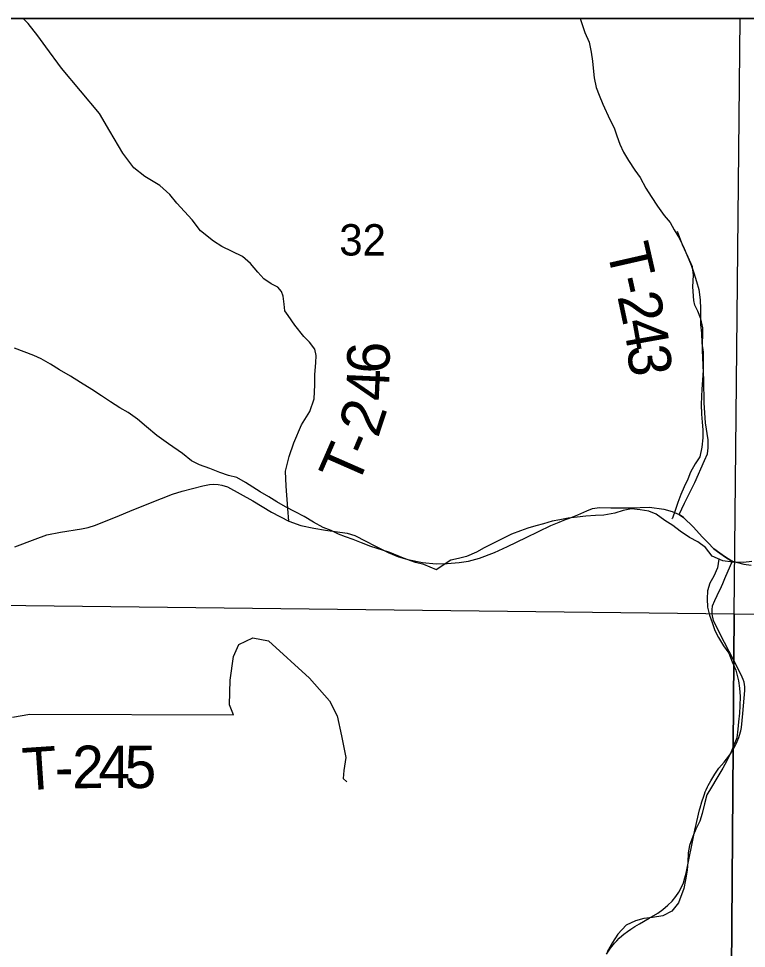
# Model space of a CAD drawing. Extents: x 0 to 34, y 0 to 22.
# Drawn here: x 6.51 to 7.482, y 19.658 to 20.9 of the extents above; entities that cross this region are included whole.
import ezdxf

# ---------------------------------------------------------------- set-up
doc = ezdxf.new("R2010")
doc.units = 0
for name, color, linetype in [('Default', 7, 'Continuous'), ('GM_X_County_Road', 7, 'Continuous'), ('GM_X_Minor_River', 7, 'Continuous'), ('GM_X_Section', 7, 'Continuous'), ('GM_X_Section_Text', 7, 'Continuous'), ('GM_X_Township_Road', 7, 'Continuous'), ('GM_X_Township_Road_Text', 7, 'Continuous'), ('SH_Cut_Line', 7, 'Continuous'), ('SH_Data', 7, 'Continuous')]:
    doc.layers.add(name, color=color, linetype=linetype)

msp = doc.modelspace()

# ---------------------------------------------------------------- linework, layer by layer
at = {"layer": 'Default'}
for p, q in [((7.8225, 20.9), (2.1, 20.9)), ((7.4735, 20.9), (6.4715, 20.9)), ((7.4653, 20.105), (7.4735, 20.9)), ((6.4665, 20.1167), (7.4653, 20.105))]:
    msp.add_line(p, q, dxfattribs=at)
at = {"layer": 'GM_X_County_Road'}
for p, q in [((6.7559, 20.2762), (6.7645, 20.2777)), ((6.7645, 20.2777), (6.77, 20.2781)), ((6.77, 20.2781), (6.7761, 20.2778)), ((6.7761, 20.2778), (6.7811, 20.277)), ((6.7811, 20.277), (6.7889, 20.2745)), ((6.6857, 20.2532), (6.7154, 20.2651)), ((6.7154, 20.2651), (6.7281, 20.2688)), ((6.7281, 20.2688), (6.7559, 20.2762)), ((6.7889, 20.2745), (6.8225, 20.2562)), ((6.6582, 20.2421), (6.6857, 20.2532)), ((6.8225, 20.2562), (6.8476, 20.2408)), ((6.6446, 20.2362), (6.6582, 20.2421)), ((6.8476, 20.2408), (6.8706, 20.2289)), ((7.2568, 20.2375), (7.2686, 20.2426)), ((7.2686, 20.2426), (7.2763, 20.2456)), ((7.2763, 20.2456), (7.2854, 20.247)), ((7.2854, 20.247), (7.3005, 20.2468)), ((7.3005, 20.2468), (7.3268, 20.2468)), ((7.3268, 20.2468), (7.3523, 20.2474)), ((7.3523, 20.2474), (7.3714, 20.2447)), ((7.3714, 20.2447), (7.3824, 20.2417)), ((7.3824, 20.2417), (7.3921, 20.2376)), ((6.6124, 20.2233), (6.6446, 20.2362)), ((6.8706, 20.2289), (6.8868, 20.2232)), ((7.2207, 20.2231), (7.2318, 20.2277)), ((7.2318, 20.2277), (7.2401, 20.2309)), ((7.2401, 20.2309), (7.2456, 20.233)), ((7.2456, 20.233), (7.2568, 20.2375)), ((7.3921, 20.2376), (7.3976, 20.2336)), ((7.3976, 20.2336), (7.411, 20.221)), ((6.5658, 20.214), (6.5935, 20.2187)), ((6.5935, 20.2187), (6.6028, 20.2202)), ((6.6028, 20.2202), (6.6124, 20.2233)), ((6.8868, 20.2232), (6.9038, 20.2194)), ((6.9038, 20.2194), (6.9197, 20.217)), ((6.9197, 20.217), (6.9484, 20.2127)), ((7.1877, 20.2069), (7.2207, 20.2231)), ((7.411, 20.221), (7.4227, 20.2079)), ((6.5048, 20.1945), (6.5319, 20.205)), ((6.5319, 20.205), (6.5475, 20.2104)), ((6.5475, 20.2104), (6.5658, 20.214)), ((6.9484, 20.2127), (6.9587, 20.2096)), ((6.9587, 20.2096), (6.9735, 20.2021)), ((7.1628, 20.1948), (7.1877, 20.2069)), ((7.4227, 20.2079), (7.4302, 20.2002)), ((6.9735, 20.2021), (6.9853, 20.1961)), ((6.9853, 20.1961), (7.0035, 20.1868)), ((7.1453, 20.1868), (7.1628, 20.1948)), ((7.4302, 20.2002), (7.4382, 20.1919)), ((7.4382, 20.1919), (7.4462, 20.1862)), ((7.0035, 20.1868), (7.0173, 20.1814)), ((7.0173, 20.1814), (7.0295, 20.1775)), ((7.1107, 20.1755), (7.1254, 20.1793)), ((7.1254, 20.1793), (7.1453, 20.1868)), ((7.4462, 20.1862), (7.4539, 20.1807)), ((7.4539, 20.1807), (7.461, 20.1765)), ((7.0295, 20.1775), (7.0492, 20.1736)), ((7.0492, 20.1736), (7.0675, 20.172)), ((7.0675, 20.172), (7.082, 20.1723)), ((7.082, 20.1723), (7.0979, 20.1735)), ((7.0979, 20.1735), (7.1107, 20.1755)), ((7.461, 20.1765), (7.463, 20.1753)), ((7.463, 20.1753), (7.4784, 20.1716)), ((7.4784, 20.1716), (7.4881, 20.1701))]:
    msp.add_line(p, q, dxfattribs=at)
at = {"layer": 'GM_X_Minor_River'}
for p, q in [((7.2598, 20.9), (7.261, 20.8959)), ((7.261, 20.8959), (7.2659, 20.8815)), ((7.2659, 20.8815), (7.2716, 20.8684)), ((7.2716, 20.8684), (7.2743, 20.8552)), ((7.2743, 20.8552), (7.2761, 20.843)), ((7.2761, 20.843), (7.2771, 20.8336)), ((7.2771, 20.8336), (7.2786, 20.8207)), ((7.2786, 20.8207), (7.2813, 20.8078)), ((7.2813, 20.8078), (7.2849, 20.7976)), ((7.2849, 20.7976), (7.2898, 20.7856)), ((7.2898, 20.7856), (7.2995, 20.7653)), ((7.2995, 20.7653), (7.3051, 20.7541)), ((7.3051, 20.7541), (7.3088, 20.7435)), ((7.3088, 20.7435), (7.3126, 20.7322)), ((7.3126, 20.7322), (7.3174, 20.7217)), ((7.3174, 20.7217), (7.3242, 20.7105)), ((7.3242, 20.7105), (7.3329, 20.6978)), ((7.3329, 20.6978), (7.34, 20.6877)), ((7.34, 20.6877), (7.3476, 20.6734)), ((7.3476, 20.6734), (7.3544, 20.6622)), ((7.3544, 20.6622), (7.3631, 20.6495)), ((7.3631, 20.6495), (7.3718, 20.6372)), ((7.3718, 20.6372), (7.38, 20.6275)), ((7.38, 20.6275), (7.3852, 20.6178)), ((7.3852, 20.6178), (7.3924, 20.6062)), ((7.3924, 20.6062), (7.3988, 20.5931)), ((7.3988, 20.5931), (7.4037, 20.5814)), ((7.4037, 20.5814), (7.4078, 20.5709)), ((7.4078, 20.5709), (7.4115, 20.5603)), ((7.4115, 20.5603), (7.4149, 20.549)), ((7.4149, 20.549), (7.4182, 20.5381)), ((7.4182, 20.5381), (7.4201, 20.5244)), ((7.4201, 20.5244), (7.4204, 20.5126)), ((7.4204, 20.5126), (7.4203, 20.5031)), ((7.4203, 20.5031), (7.4206, 20.4917)), ((7.4206, 20.4917), (7.4217, 20.48)), ((7.4217, 20.48), (7.4224, 20.4667)), ((7.4224, 20.4667), (7.4239, 20.4545)), ((6.5171, 20.4551), (6.504, 20.46)), ((6.5298, 20.4502), (6.5171, 20.4551)), ((7.4239, 20.4545), (7.4238, 20.4439)), ((6.5398, 20.4455), (6.5298, 20.4502)), ((6.5522, 20.4383), (6.5398, 20.4455)), ((7.4238, 20.4439), (7.4238, 20.4306)), ((6.5642, 20.4311), (6.5522, 20.4383)), ((6.579, 20.4224), (6.5642, 20.4311)), ((7.4238, 20.4306), (7.423, 20.4172)), ((6.5925, 20.4141), (6.579, 20.4224)), ((6.6076, 20.4047), (6.5925, 20.4141)), ((7.423, 20.4172), (7.4222, 20.4051)), ((6.6205, 20.3964), (6.6076, 20.4047)), ((7.4222, 20.4051), (7.4217, 20.3952)), ((6.6325, 20.3884), (6.6205, 20.3964)), ((7.4217, 20.3952), (7.4213, 20.3845)), ((6.6449, 20.3804), (6.6325, 20.3884)), ((6.6558, 20.3739), (6.6449, 20.3804)), ((7.4213, 20.3845), (7.422, 20.3716)), ((6.6686, 20.3652), (6.6558, 20.3739)), ((6.6803, 20.3549), (6.6686, 20.3652)), ((7.422, 20.3716), (7.4227, 20.361)), ((6.6944, 20.3432), (6.6803, 20.3549)), ((7.4227, 20.361), (7.4237, 20.3507)), ((6.7099, 20.3323), (6.6944, 20.3432)), ((7.4236, 20.3401), (7.4224, 20.3275)), ((7.4237, 20.3507), (7.4236, 20.3401)), ((6.7286, 20.3192), (6.7099, 20.3323)), ((7.4224, 20.3275), (7.4197, 20.3149)), ((6.7407, 20.3093), (6.7286, 20.3192)), ((7.4197, 20.3149), (7.4135, 20.3052)), ((6.7515, 20.3039), (6.7407, 20.3093)), ((6.7649, 20.299), (6.7515, 20.3039)), ((7.4135, 20.3052), (7.407, 20.2944)), ((6.7784, 20.2937), (6.7649, 20.299)), ((6.7899, 20.2899), (6.7784, 20.2937)), ((6.8011, 20.2872), (6.7899, 20.2899)), ((7.407, 20.2944), (7.4035, 20.2848)), ((6.8127, 20.2807), (6.8011, 20.2872)), ((6.8224, 20.2742), (6.8127, 20.2807)), ((7.4035, 20.2848), (7.3988, 20.2747)), ((6.8325, 20.268), (6.8224, 20.2742)), ((6.8437, 20.2612), (6.8325, 20.268)), ((7.3988, 20.2747), (7.3941, 20.2643)), ((6.8545, 20.2547), (6.8437, 20.2612)), ((6.8662, 20.2478), (6.8545, 20.2547)), ((7.3902, 20.254), (7.3867, 20.2432)), ((7.3941, 20.2643), (7.3902, 20.254)), ((6.8789, 20.2414), (6.8662, 20.2478)), ((6.8913, 20.2349), (6.8789, 20.2414)), ((7.3172, 20.2432), (7.3059, 20.2395)), ((7.3285, 20.2451), (7.3172, 20.2432)), ((7.34, 20.2442), (7.3285, 20.2451)), ((7.3514, 20.2423), (7.34, 20.2442)), ((7.3614, 20.238), (7.3514, 20.2423)), ((7.3867, 20.2432), (7.3832, 20.2329)), ((6.9037, 20.2277), (6.8913, 20.2349)), ((6.9164, 20.2205), (6.9037, 20.2277)), ((7.2222, 20.2289), (7.2109, 20.2255)), ((7.2324, 20.2307), (7.2222, 20.2289)), ((7.2437, 20.2329), (7.2324, 20.2307)), ((7.2555, 20.2343), (7.2437, 20.2329)), ((7.2672, 20.2354), (7.2555, 20.2343)), ((7.2801, 20.2362), (7.2672, 20.2354)), ((7.2915, 20.2368), (7.2801, 20.2362)), ((7.3059, 20.2395), (7.2915, 20.2368)), ((7.3727, 20.2299), (7.3614, 20.238)), ((7.3835, 20.223), (7.3727, 20.2299)), ((7.3832, 20.2329), (7.3821, 20.2321)), ((6.9272, 20.2163), (6.9164, 20.2205)), ((6.9369, 20.2116), (6.9272, 20.2163)), ((7.18, 20.2159), (7.1679, 20.2114)), ((7.1898, 20.2193), (7.18, 20.2159)), ((7.2007, 20.2226), (7.1898, 20.2193)), ((7.2109, 20.2255), (7.2007, 20.2226)), ((7.3932, 20.2153), (7.3835, 20.223)), ((7.4056, 20.2072), (7.3932, 20.2153)), ((6.9465, 20.2081), (6.9369, 20.2116)), ((6.9565, 20.2042), (6.9465, 20.2081)), ((6.9677, 20.1997), (6.9565, 20.2042)), ((7.1679, 20.2114), (7.1439, 20.1994)), ((7.4171, 20.2011), (7.4056, 20.2072)), ((6.98, 20.1951), (6.9677, 20.1997)), ((6.9957, 20.1899), (6.98, 20.1951)), ((7.1316, 20.1933), (7.1211, 20.1874)), ((7.1439, 20.1994), (7.1316, 20.1933)), ((7.4272, 20.1937), (7.4171, 20.2011)), ((7.4359, 20.1822), (7.4272, 20.1937)), ((7.0053, 20.1868), (6.9957, 20.1899)), ((7.0238, 20.1794), (7.0053, 20.1868)), ((7.0396, 20.1738), (7.0238, 20.1794)), ((7.0974, 20.1791), (7.0868, 20.1769)), ((7.1079, 20.1817), (7.0974, 20.1791)), ((7.1211, 20.1874), (7.1079, 20.1817)), ((7.4501, 20.1757), (7.4359, 20.1822)), ((7.445, 20.1781), (7.4432, 20.1664)), ((7.0507, 20.1711), (7.0396, 20.1738)), ((7.0677, 20.1637), (7.0507, 20.1711)), ((7.0868, 20.1769), (7.0676, 20.1637)), ((7.4432, 20.1664), (7.4382, 20.1556)), ((7.4631, 20.1742), (7.4501, 20.1757)), ((7.4779, 20.1738), (7.4631, 20.1742)), ((7.4889, 20.1749), (7.4779, 20.1738)), ((7.4382, 20.1556), (7.4327, 20.146)), ((7.4327, 20.146), (7.43, 20.1356)), ((7.43, 20.1356), (7.4295, 20.125)), ((7.4295, 20.125), (7.4298, 20.1139)), ((7.4298, 20.1139), (7.4324, 20.1034)), ((7.4324, 20.1034), (7.436, 20.0936)), ((7.436, 20.0936), (7.4398, 20.083)), ((7.4398, 20.083), (7.4446, 20.0733)), ((7.4446, 20.0733), (7.451, 20.0624)), ((7.451, 20.0624), (7.4581, 20.0527)), ((7.4581, 20.0527), (7.4629, 20.0411)), ((7.4629, 20.0411), (7.4678, 20.0298)), ((7.4678, 20.0298), (7.4712, 20.0158)), ((7.4712, 20.0158), (7.4726, 20.0059)), ((7.4726, 20.0059), (7.4733, 19.9946)), ((7.4733, 19.9946), (7.4729, 19.9824)), ((7.4729, 19.9824), (7.4724, 19.9725)), ((7.4724, 19.9725), (7.4712, 19.9607)), ((7.4712, 19.9607), (7.4703, 19.9511)), ((7.4703, 19.9511), (7.4688, 19.9393)), ((7.4652, 19.9297), (7.4606, 19.9185)), ((7.4688, 19.9393), (7.4652, 19.9297)), ((7.4606, 19.9185), (7.4555, 19.9089)), ((7.4555, 19.9089), (7.4501, 19.8992)), ((7.4501, 19.8992), (7.4421, 19.8857)), ((7.4421, 19.8857), (7.4352, 19.8737)), ((7.4352, 19.8737), (7.429, 19.8633)), ((7.429, 19.8633), (7.4256, 19.8514)), ((7.4256, 19.8514), (7.4229, 19.8384)), ((7.4229, 19.8384), (7.4194, 19.828)), ((7.4143, 19.8176), (7.41, 19.8076)), ((7.4194, 19.828), (7.4143, 19.8176)), ((7.41, 19.8076), (7.4058, 19.7957)), ((7.4058, 19.7957), (7.4038, 19.7858)), ((7.4038, 19.7858), (7.4034, 19.7736)), ((7.4034, 19.7736), (7.4025, 19.7629)), ((7.4025, 19.7629), (7.4002, 19.7499)), ((7.4002, 19.7499), (7.3982, 19.7381)), ((7.3982, 19.7381), (7.3912, 19.7193)), ((7.3912, 19.7193), (7.3823, 19.708)), ((7.3823, 19.708), (7.37, 19.702)), ((7.3337, 19.6953), (7.3213, 19.6892)), ((7.3446, 19.6982), (7.3337, 19.6953)), ((7.3564, 19.6997), (7.3446, 19.6982)), ((7.37, 19.702), (7.3564, 19.6997)), ((7.3213, 19.6892), (7.3102, 19.6775)), ((7.3102, 19.6775), (7.3029, 19.6663)), ((7.3029, 19.6663), (7.2957, 19.6535))]:
    msp.add_line(p, q, dxfattribs=at)
at = {"layer": 'GM_X_Section'}
for p, q in [((6.4665, 20.1167), (7.4653, 20.105)), ((7.4653, 20.105), (7.4585, 19.1081)), ((7.4585, 19.1081), (7.4653, 20.105)), ((7.4653, 20.105), (8.4603, 20.0986))]:
    msp.add_line(p, q, dxfattribs=at)
at = {"layer": 'GM_X_Township_Road'}
for p, q in [((6.5226, 20.8933), (6.5158, 20.9)), ((6.5353, 20.8771), (6.5226, 20.8933)), ((6.5462, 20.8621), (6.5353, 20.8771)), ((6.567, 20.8337), (6.5462, 20.8621)), ((6.6178, 20.7731), (6.567, 20.8337)), ((6.6317, 20.7498), (6.6178, 20.7731)), ((6.6487, 20.7204), (6.6317, 20.7498)), ((6.6636, 20.7009), (6.6487, 20.7204)), ((6.6782, 20.6892), (6.6636, 20.7009)), ((6.6982, 20.6772), (6.6782, 20.6892)), ((6.7115, 20.6653), (6.6982, 20.6772)), ((6.7211, 20.6534), (6.7115, 20.6653)), ((6.7416, 20.6313), (6.7211, 20.6534)), ((6.7526, 20.6166), (6.7416, 20.6313)), ((6.7698, 20.6026), (6.7526, 20.6166)), ((7.3964, 20.5977), (7.3897, 20.6159)), ((6.7811, 20.5956), (6.7698, 20.6026)), ((6.8088, 20.5825), (6.7811, 20.5956)), ((7.4041, 20.5814), (7.3964, 20.5977)), ((6.8196, 20.5729), (6.8088, 20.5825)), ((7.4099, 20.5683), (7.4041, 20.5814)), ((6.8292, 20.5615), (6.8196, 20.5729)), ((7.411, 20.5574), (7.4099, 20.5683)), ((6.8372, 20.5525), (6.8292, 20.5615)), ((6.8472, 20.5459), (6.8372, 20.5525)), ((7.4104, 20.542), (7.411, 20.5574)), ((6.8557, 20.5412), (6.8472, 20.5459)), ((6.8608, 20.5354), (6.8557, 20.5412)), ((7.4116, 20.5237), (7.4104, 20.542)), ((6.8629, 20.5295), (6.8608, 20.5354)), ((6.8644, 20.5188), (6.8629, 20.5295)), ((6.8651, 20.5097), (6.8644, 20.5188)), ((7.413, 20.5171), (7.4116, 20.5237)), ((7.4167, 20.5091), (7.413, 20.5171)), ((6.8698, 20.5035), (6.8651, 20.5097)), ((6.8787, 20.4905), (6.8698, 20.5035)), ((7.4207, 20.4991), (7.4167, 20.5091)), ((6.8905, 20.4756), (6.8787, 20.4905)), ((7.4236, 20.4871), (7.4207, 20.4991)), ((6.8983, 20.4679), (6.8905, 20.4756)), ((7.4233, 20.4573), (7.4236, 20.4871)), ((6.9053, 20.4586), (6.8983, 20.4679)), ((6.9073, 20.4501), (6.9053, 20.4586)), ((7.4247, 20.4173), (7.4233, 20.4573)), ((6.9052, 20.4246), (6.9066, 20.4401)), ((6.9066, 20.4401), (6.9073, 20.4501)), ((6.9055, 20.4111), (6.9052, 20.4246)), ((7.4253, 20.3867), (7.4247, 20.4173)), ((6.9044, 20.3923), (6.9055, 20.4111)), ((6.8986, 20.3753), (6.9044, 20.3923)), ((7.4273, 20.3603), (7.4253, 20.3867)), ((6.8876, 20.3573), (6.8986, 20.3753)), ((6.8774, 20.3334), (6.8876, 20.3573)), ((7.4308, 20.3375), (7.4273, 20.3603)), ((6.8711, 20.3151), (6.8774, 20.3334)), ((7.4296, 20.3186), (7.4308, 20.3269)), ((7.4308, 20.3269), (7.4308, 20.3375)), ((6.8662, 20.2956), (6.8711, 20.3151)), ((7.4259, 20.3097), (7.4296, 20.3186)), ((7.4127, 20.2805), (7.4259, 20.3097)), ((6.8671, 20.2758), (6.8662, 20.2956)), ((7.3993, 20.2531), (7.4127, 20.2805)), ((6.8691, 20.2459), (6.8671, 20.2758)), ((7.3921, 20.2376), (7.3993, 20.2531)), ((6.8706, 20.2289), (6.8691, 20.2459)), ((7.3976, 20.2336), (7.3921, 20.2376)), ((7.411, 20.221), (7.3976, 20.2336)), ((7.4227, 20.2079), (7.411, 20.221)), ((7.4302, 20.2002), (7.4227, 20.2079)), ((7.4382, 20.1919), (7.4302, 20.2002)), ((7.4462, 20.1862), (7.4382, 20.1919)), ((7.4539, 20.1807), (7.4462, 20.1862)), ((7.461, 20.1765), (7.4539, 20.1807)), ((7.453, 20.1525), (7.4605, 20.1697)), ((7.4605, 20.1697), (7.463, 20.1753)), ((7.463, 20.1753), (7.461, 20.1765)), ((7.4426, 20.1297), (7.4483, 20.1417)), ((7.4483, 20.1417), (7.4502, 20.1458)), ((7.4502, 20.1458), (7.453, 20.1525)), ((7.4395, 20.1231), (7.4426, 20.1297)), ((7.4363, 20.114), (7.4367, 20.1157)), ((7.4367, 20.1157), (7.4395, 20.1231)), ((7.4359, 20.1106), (7.436, 20.1124)), ((7.4359, 20.1084), (7.4359, 20.1106)), ((7.4361, 20.1053), (7.4359, 20.1084)), ((7.436, 20.1124), (7.4363, 20.114)), ((7.4364, 20.1023), (7.4361, 20.1053)), ((7.4372, 20.0986), (7.4364, 20.1023)), ((7.438, 20.096), (7.4372, 20.0986)), ((7.4391, 20.0929), (7.438, 20.096)), ((7.4524, 20.0667), (7.4391, 20.0929)), ((6.8036, 20.0641), (6.8225, 20.0729)), ((6.8225, 20.0729), (6.8435, 20.0689)), ((6.8435, 20.0689), (6.8983, 20.019)), ((7.4715, 20.0299), (7.4524, 20.0667)), ((6.7968, 20.0483), (6.8036, 20.0641)), ((6.7921, 20.0166), (6.7968, 20.0483)), ((7.4761, 20.0203), (7.4715, 20.0299)), ((6.7913, 19.9835), (6.7921, 20.0166)), ((6.8983, 20.019), (6.925, 19.989)), ((7.4773, 20.0173), (7.4761, 20.0203)), ((7.4786, 20.0139), (7.4773, 20.0173)), ((7.4793, 20.0109), (7.4786, 20.0139)), ((7.4796, 20.0076), (7.4793, 20.0109)), ((7.4798, 20.0026), (7.4796, 20.0076)), ((7.4768, 19.9719), (7.4798, 20.0026)), ((6.7965, 19.9704), (6.7913, 19.9835)), ((6.925, 19.989), (6.935, 19.969)), ((6.5016, 19.9672), (6.5245, 19.9709)), ((6.5245, 19.9709), (6.7965, 19.9704)), ((6.935, 19.969), (6.9411, 19.9423)), ((7.475, 19.9531), (7.4768, 19.9719)), ((6.9411, 19.9423), (6.9469, 19.9133)), ((7.4715, 19.9399), (7.4726, 19.943)), ((7.4726, 19.943), (7.4743, 19.9489)), ((7.4743, 19.9489), (7.475, 19.9531)), ((7.4661, 19.9278), (7.468, 19.9314)), ((7.468, 19.9314), (7.4715, 19.9399)), ((7.4582, 19.9148), (7.4606, 19.9182)), ((7.4606, 19.9182), (7.4661, 19.9278)), ((6.9469, 19.9133), (6.9439, 19.8961)), ((7.4449, 19.8988), (7.4521, 19.9069)), ((7.4521, 19.9069), (7.4582, 19.9148)), ((6.9439, 19.8961), (6.9432, 19.8851)), ((7.4396, 19.891), (7.4449, 19.8988)), ((6.9432, 19.8851), (6.948, 19.8807)), ((7.4309, 19.8758), (7.4342, 19.8819)), ((7.4342, 19.8819), (7.4396, 19.891)), ((7.4258, 19.8643), (7.4269, 19.8673)), ((7.4269, 19.8673), (7.4281, 19.8701)), ((7.4281, 19.8701), (7.4298, 19.8739)), ((7.4298, 19.8739), (7.4309, 19.8758)), ((7.4222, 19.8539), (7.4247, 19.8614)), ((7.4247, 19.8614), (7.4258, 19.8643)), ((7.4178, 19.8375), (7.4193, 19.8435)), ((7.4193, 19.8435), (7.4199, 19.846)), ((7.4199, 19.846), (7.4222, 19.8539)), ((7.4146, 19.8237), (7.4178, 19.8375)), ((7.413, 19.8163), (7.4146, 19.8237)), ((7.4011, 19.7586), (7.413, 19.8163)), ((7.3995, 19.7524), (7.4011, 19.7586)), ((7.3946, 19.739), (7.3976, 19.746)), ((7.3976, 19.746), (7.3995, 19.7524)), ((7.3877, 19.7278), (7.3916, 19.7335)), ((7.3916, 19.7335), (7.3946, 19.739)), ((7.3767, 19.7159), (7.3824, 19.7216)), ((7.3824, 19.7216), (7.3877, 19.7278)), ((7.3634, 19.7055), (7.37, 19.7102)), ((7.37, 19.7102), (7.3767, 19.7159)), ((7.3388, 19.691), (7.3521, 19.6988)), ((7.3521, 19.6988), (7.3634, 19.7055)), ((7.3182, 19.6772), (7.3231, 19.6809)), ((7.3231, 19.6809), (7.3276, 19.6841)), ((7.3276, 19.6841), (7.3327, 19.6875)), ((7.3327, 19.6875), (7.3388, 19.691)), ((7.3085, 19.6683), (7.312, 19.6718)), ((7.312, 19.6718), (7.3155, 19.6749)), ((7.3155, 19.6749), (7.3182, 19.6772)), ((7.295, 19.6508), (7.3004, 19.6588)), ((7.3004, 19.6588), (7.3055, 19.6651)), ((7.3055, 19.6651), (7.3085, 19.6683))]:
    msp.add_line(p, q, dxfattribs=at)
at = {"layer": 'SH_Cut_Line'}
msp.add_line((7.8225, 20.9), (2.1, 20.9), dxfattribs=at)
at = {"layer": 'SH_Data'}
msp.add_line((2.1, 20.9), (8.9, 20.9), dxfattribs=at)

# ---------------------------------------------------------------- texts
at = {"layer": 'GM_X_Section_Text'}
msp.add_text('32', height=0.04186, rotation=0, dxfattribs=at).set_placement((6.938, 20.5836))
at = {"layer": 'GM_X_Township_Road_Text'}
for s, rotation, p in [('T', 282.791, (7.2947, 20.5933)), ('-', 282.6219, (7.3041, 20.5519)), ('2', 282.0101, (7.3092, 20.5293)), ('4', 280.1647, (7.3164, 20.4955)), ('6', 89.6501, (7.0052, 20.426)), ('3', 275.6868, (7.3224, 20.4622)), ('4', 87.4152, (7.0035, 20.3887)), ('2', 71.6876, (6.9895, 20.3388)), ('-', 66.8979, (6.9785, 20.3125)), ('T', 66.3073, (6.9612, 20.273)), ('2', 0.2498, (6.5814, 19.8722)), ('T', 3.8557, (6.5166, 19.869)), ('4', 0.0416, (6.6164, 19.8724)), ('5', 0.0052, (6.6513, 19.8724)), ('-', 0.8275, (6.5582, 19.8719))]:
    msp.add_text(s, height=0.0568, rotation=rotation, dxfattribs=at).set_placement(p)

doc.saveas('drawing.dxf')
